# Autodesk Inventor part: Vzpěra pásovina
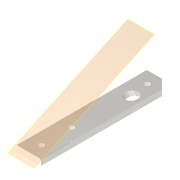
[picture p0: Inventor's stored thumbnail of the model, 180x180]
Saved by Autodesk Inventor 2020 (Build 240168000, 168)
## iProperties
Created: 2025-03
Part Number: Vzpěra pásovina
Material: Ocel
Document SubType Name: Modeling
Designer: doma
Density: 7.85 g/cm^3
Appearance: Ocel
Mass: 624.076 g
Surface Area: 224.537 cm^2
Volume: 79.5001 cm^3
Author: doma
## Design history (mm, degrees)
sketch "Náčrt1"
  geometry: L1 (-20, -5)-(20, -5); L2 (20, -5)-(20, 5); L3 (20, 5)-(-20, 5); L4 (-20, 5)-(-20, -5); L5 (-20, -5)-(20, 5); L6 (20, -5)-(-20, 5); 1 further point
  constraints: 12 end point, 2 midpoint, 2 parallel, 1 horizontal, 1 perpendicular
  dimensions: "d0" = 40 distance of L3.end L2.end; "d1" = 10 distance of L2.end L1.end
extrude "Vysunutí1" new body sketch "Náčrt1" distance "d2" = 215; taper "d3" = 0 deg
sketch "Náčrt2"
  geometry: L1 (20, 0)-(20, -215); L2 (0, -215)-(40, -215) reference; L3 (40, 0)-(0, 0) reference; 3 further points
  constraints: 3 point on line, 2 end point, 1 midpoint
  dimensions: "d4" = 20 distance from line of L2 point (20, -195); "d5" = 50 distance of point (20, -145) point (20, -195); "d6" = 20 distance from line of L3 point (20, -20)
hole "Díra1" sketch "Náčrt2" at (20, -195), (20, -145), (20, -20) diameter "d7" = 9; stored, may be unused: countersink angle "d11" = 90 deg, drill point angle "d13" = 118 deg; dims "d8" = 6, "d9" = 4, "d10" = 2, "d12" = 8
chamfer "Zkosení1" distance "d14" = 15; stored, may be unused: second distance "d15" = 2, angle "d16" = 45 deg
node "Pracovní rovina1"
sketch "Náčrt3"
  geometry: C1 r 10 at (16, -150) reference; 1 further point
extrude "Vysunutí2" cut sketch "Náčrt3" extent not by distance; stored distance "d18" = 0; taper "d19" = 0 deg
chamfer "Zkosení2" distance "d20" = 2; stored, may be unused: second distance "d21" = 2, angle "d22" = 45 deg; dims "d23" = 150, "d24" = 50, "d25" = 0
node "Těleso1"
node "Referenční1"
other parameters: "d17" = -25 deg
